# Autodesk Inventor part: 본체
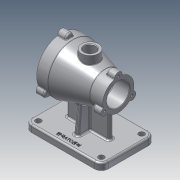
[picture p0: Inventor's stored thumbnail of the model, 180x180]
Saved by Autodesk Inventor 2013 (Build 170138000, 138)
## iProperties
Created: 2020-03
Part Number: 본체
Material: 알루미늄 6061
Document SubType Name: Modeling
Designer: user
Density: 2.71 g/cm^3
Mass: 998.506 g
Surface Area: 864.159 cm^2
Volume: 368.452 cm^3
Author: user
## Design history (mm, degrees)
sketch "스케치1"
  geometry: L1 (-50, 0)-(50, 0); L2 (-50, 0)-(-50, 44); L3 (-50, 44)-(-30, 44); L4 (-30, 44)-(27, 27.5); L5 (27, 27.5)-(50, 27.5); L6 (50, 27.5)-(50, 0); 2 further points
  constraints: 12 end point, 3 perpendicular, 1 coincident, 1 horizontal, 1 midpoint, 1 parallel
  dimensions: "d0" = 100 distance of L1.start L1.end; "d2" = 20 distance of L2.end L3.end; "d3" = 77 distance from line of L4.end L2; "d4" = 88 diameter of L3 L1; "d5" = 55 diameter of L5 L1
revolve "회전1" sketch "스케치1" stored, may be unused: angle "d6" = 90 deg
node "작업 평면1"
sketch "스케치2"
  geometry: L1 (-67.5, 47.5)-(67.5, 47.5); L2 (67.5, 47.5)-(67.5, -47.5); L3 (67.5, -47.5)-(-67.5, -47.5); L4 (-67.5, -47.5)-(-67.5, 47.5); L5 (-67.5, 47.5)-(67.5, -47.5); L6 (67.5, 47.5)-(-67.5, -47.5); 1 further point
  constraints: 12 end point, 2 midpoint, 2 parallel, 1 horizontal, 1 perpendicular
  dimensions: "d8" = 135 distance of L1.start L1.end; "d10" = 95 distance of L1.end L2.end
extrude "돌출1" join sketch "스케치2" distance "d11" = 12; taper "d12" = 0 deg
fillet "모깎기1" dims "d13" = 12
sketch "스케치3"
  geometry: C1 r 5 at (-55.5, 35.5); A1 r 12 centre (-55.5, 35.5) between (-55.5, 47.5) and (-67.5, 35.5) reference; 1 further point
  constraints: 1 centre point, 1 coincident
  dimensions: "d14" = 10 diameter of C1
extrude "돌출2" cut sketch "스케치3" distance "d16" = 12; taper "d17" = 0 deg
sketch "스케치4"
  geometry: L1 (-50, -44)-(-50, 44) reference; L2 (-50, 44)-(-30, 44) reference; L3 (-30, 44)-(27, 27.5) reference; L4 (27, 27.5)-(50, 27.5) reference; L5 (50, 27.5)-(50, -27.5) reference; L6 (50, -27.5)-(27, -27.5) reference; L7 (27, -27.5)-(-30, -44) reference; L8 (-30, -44)-(-50, -44) reference; L9 (-67.5, -75)-(67.5, -75) reference; L10 (67.5, -75)-(67.5, -87) reference; L11 (67.5, -87)-(-67.5, -87) reference; L12 (-67.5, -87)-(-67.5, -75) reference; L13 (-37, -75)-(-37, 0); L14 (-37, 0)-(37, 0); L15 (37, 0)-(37, -75); L16 (-37, -75)-(37, -75); 2 further points
  constraints: 8 end point, 2 perpendicular, 2 point on line, 1 coincident, 1 collinear, 1 midpoint, 1 parallel
  dimensions: "d18" = 37 distance from line of point (0, 0) L13; "d19" = 37 distance from line of L15 point (0, 0) (derived)
extrude "돌출3" join sketch "스케치4" stored distance "d20" = 8; taper "d21" = 0 deg
sketch "스케치5"
  geometry: L1 (0, 18.438)-(0, -18.438); L2 (0, 18.438)-(-75, 25); L3 (-75, 25)-(-75, -25); L4 (-75, -25)-(0, -18.438); L5 (-75, 4)-(-75, -4) reference; L6 (-75, -30.5)-(-75, -40.5) reference; 3 further points
  constraints: 8 end point, 3 midpoint, 1 coincident, 1 parallel, 1 vertical
  dimensions: "d22" = 50 distance of L2.end L3.end; "d24" = 95 deg angle of L6 L4
extrude "돌출4" join sketch "스케치5" stored distance "d26" = 8; taper "d27" = 0 deg
node "작업 평면2"
sketch "스케치6"
  geometry: C1 r 15 at (0, 0); 1 further point
  constraints: 1 centre point, 1 coincident
  dimensions: "d29" = 30 diameter of C1
extrude "돌출5" join sketch "스케치6" stored distance "d31" = 8; taper "d32" = 0 deg
sketch "스케치7"
  geometry: C1 r 15 at (0, 0) reference; C2 r 10 at (0, 0)
  constraints: 1 centre point
  dimensions: "d33" = 20 diameter of C2
extrude "돌출6" cut sketch "스케치7" distance "d35" = 25; taper "d36" = 0 deg
sketch "스케치8"
  geometry: L1 (-50, 0)-(50, 0); L2 (-50, 0)-(-50, 36); L3 (-50, 36)-(-27, 36); L4 (-27, 36)-(-27, 26); L5 (-27, 26)-(20, 26); L6 (20, 26)-(20, 20); L7 (20, 20)-(50, 20); L8 (50, 20)-(50, 0); 2 further points
  constraints: 16 end point, 4 perpendicular, 3 parallel, 1 coincident, 1 horizontal, 1 midpoint
  dimensions: "d37" = 100 distance of L1.start L1.end; "d39" = 72 diameter of L3 L1; "d40" = 52 diameter of L5 L1; "d41" = 40 diameter of L7 L1; "d42" = 30 distance of L6.end L7.end; "d43" = 47 distance of L4.end L5.end; "d44" = 23 distance of L2.end L3.end (derived)
revolve "회전2" sketch "스케치8" stored, may be unused: angle "d45" = 90 deg
sketch "스케치9"
  geometry: C1 r 36 at (0, 0) reference; C2 r 44 at (0, 0); C3 r 7 at (0, 44); 1 further point
  constraints: 2 centre point, 2 vertical alignment, 1 coincident, 1 other
  dimensions: "d46" = 88 diameter of C2; "d48" = 14 diameter of C3
extrude "돌출7" join sketch "스케치9" distance "d49" = 15; taper "d50" = 0 deg
sketch "스케치10"
  geometry: A1 r 7 centre (0, 0) between (6.978, -0.557) and (-6.978, -0.557) reference; 1 further point
  constraints: 1 coincident
hole "구멍1" sketch "스케치10" at (0, 0) diameter "d51" = 4.134; stored, may be unused: countersink angle "d55" = 90 deg, drill point angle "d57" = 118 deg; dims "d52" = 9, "d53" = 4, "d54" = 2, "d56" = 11
fillet "모깎기2" dims "d58" = 3
fillet "모깎기3" dims "d59" = 1
fillet "모깎기4" dims "d63" = 3
fillet "모깎기5" dims "d64" = 3
sketch "스케치11"
  geometry: C1 r 20 at (0, 0) reference; C2 r 7 at (0, 27.5); 1 further point
  constraints: 2 vertical alignment, 1 centre point, 1 other
  dimensions: "d65" = 14 diameter of C2
extrude "돌출8" join sketch "스케치11" distance "d67" = 15; taper "d68" = 0 deg
sketch "스케치12"
  geometry: A1 r 7 centre (0, 0) between (6.943, -0.891) and (-6.943, -0.891) reference; 1 further point
  constraints: 1 coincident
hole "구멍2" sketch "스케치12" at (0, 0) diameter "d69" = 4.134; stored, may be unused: countersink angle "d73" = 90 deg, drill point angle "d75" = 118 deg; dims "d70" = 9, "d71" = 4, "d72" = 2, "d74" = 11
fillet "모깎기6" dims "d76" = 3
fillet "모깎기7" dims "d77" = 1
fillet "모깎기8" dims "d81" = 3
fillet "모깎기9" dims "d82" = 3
fillet "모깎기10" dims "d83" = 3
node "작업 평면3"
sketch "스케치13"
  geometry: L1 (55.5, 47.5)-(-55.5, 47.5) reference; 2 further points
  constraints: 1 vertical alignment, 1 other
  dimensions: "d85" = 10 distance from line of L1 point (0, 37.5)
feature "엠보싱1" sketch "스케치13" dims "d0" = 100, "d2" = 20, "d3" = 77, "d4" = 88, "d5" = 55, "d86" = 0.5, "d87" = 0
chamfer "모따기1" distance "d88" = 1; stored, may be unused: second distance "d89" = 2, angle "d90" = 45 deg
fillet "모깎기11" dims "d91" = 3
chamfer "모따기2" distance "d92" = 1; stored, may be unused: second distance "d93" = 2, angle "d94" = 45 deg
fillet "모깎기12" dims "d95" = 1
node "솔리드1"
mirror "대칭1"
mirror "대칭2"
pattern_circular "원형 패턴1" dims "d61" = 360 deg
pattern_circular "원형 패턴2" dims "d79" = 360 deg
node "절단 모서리 투영1"
other parameters: "d7" = -87, "d28" = 45, "d84" = -54.75
